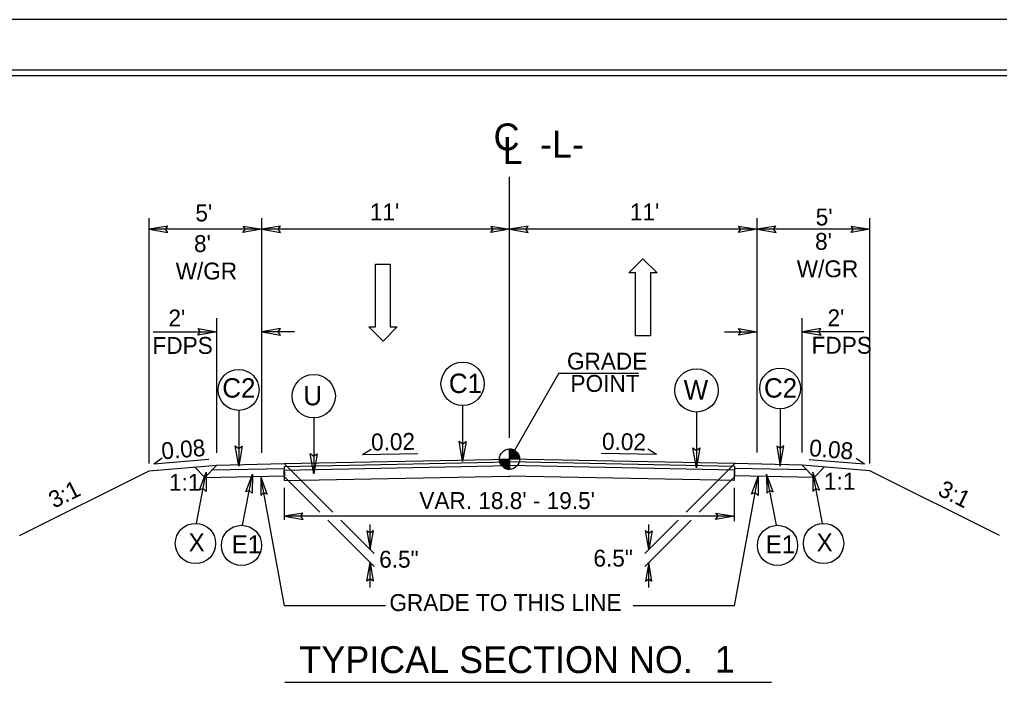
# Model space of a CAD drawing. Extents: x 60664 to 60833, y 51234 to 51344.
# Drawn here: x 60735.82 to 60779.32, y 51314.31 to 51344.41 of the extents above; entities that cross this region are included whole.
import ezdxf

# ---------------------------------------------------------------- set-up
doc = ezdxf.new("R2010")
doc.units = 0
for name, color, linetype in [('Exist XS Ground Line', 7, 'Continuous'), ('Prop Dimension', 7, 'Continuous'), ('Prop Dimension Text', 7, 'Continuous'), ('Prop Lane Arrow CELL', 7, 'Continuous'), ('Sheet Cutting Line CELL', 7, 'Continuous'), ('Sheet Plot Border Inside CELL', 7, 'Continuous'), ('Sheet Plot Border Outside CELL', 7, 'Continuous'), ('Sheet Typical CELL', 7, 'Continuous'), ('Typical Grade Point Symbol CELL', 7, 'Continuous'), ('Typical ID Circle CELL', 7, 'Continuous'), ('Typical Pavement Slope CELL', 7, 'Continuous'), ('Typical Pavement Slope Information CELL', 7, 'Continuous'), ('Typical Shoulder Slope CELL', 7, 'Continuous'), ('Typical Shoulder Slope Information CELL', 7, 'Continuous'), ('Typical Slope Point Local CELL', 7, 'Continuous'), ('Typical Terminator CELL', 7, 'Continuous'), ('Typical Text General CELL', 7, 'Continuous'), ('Typical Text Grade Point CELL', 7, 'Continuous'), ('Typical Text ID Circle CELL', 7, 'Continuous'), ('Typical Text Label CELL', 7, 'Continuous')]:
    doc.layers.add(name, color=color, linetype=linetype)

msp = doc.modelspace()

# ---------------------------------------------------------------- linework, layer by layer
at = {"layer": 'Exist XS Ground Line'}
for p, q in [((60747.573, 51324.403), (60757.576, 51324.603)), ((60747.577, 51323.941), (60747.573, 51324.403)), ((60767.567, 51324.403), (60757.568, 51324.603)), ((60767.557, 51323.941), (60767.567, 51324.403)), ((60747.575, 51323.941), (60757.585, 51324.141)), ((60767.557, 51323.941), (60757.559, 51324.141))]:
    msp.add_line(p, q, dxfattribs=at)
at = {"layer": 'Prop Dimension'}
for p, q in [((60757.572, 51325.837), (60757.572, 51337.419)), ((60746.572, 51325.17), (60746.572, 51335.597)), ((60768.572, 51325.189), (60768.572, 51335.597)), ((60746.572, 51335.097), (60741.572, 51335.097)), ((60757.572, 51335.097), (60746.572, 51335.097)), ((60768.572, 51335.097), (60757.572, 51335.097)), ((60773.572, 51335.097), (60768.572, 51335.097)), ((60744.572, 51325.17), (60744.572, 51331.152)), ((60770.572, 51325.189), (60770.572, 51331.152)), ((60741.755, 51330.542), (60744.572, 51330.542)), ((60748.03, 51330.542), (60746.572, 51330.542)), ((60767.114, 51330.542), (60768.572, 51330.542)), ((60773.298, 51330.542), (60770.572, 51330.542)), ((60747.572, 51324.689), (60749.729, 51322.533)), ((60767.571, 51324.689), (60765.414, 51322.533)), ((60747.575, 51318.373), (60746.528, 51324.126)), ((60747.575, 51324.106), (60749.148, 51322.532)), ((60767.559, 51324.106), (60765.986, 51322.533)), ((60767.566, 51318.373), (60768.613, 51324.126)), ((60747.575, 51322.194), (60747.575, 51323.616)), ((60767.557, 51322.132), (60767.557, 51323.617)), ((60767.557, 51322.351), (60747.575, 51322.351)), ((60749.502, 51322.179), (60751.556, 51320.125)), ((60750.082, 51322.179), (60751.556, 51320.705)), ((60765.632, 51322.179), (60763.578, 51320.125)), ((60765.061, 51322.179), (60763.587, 51320.705)), ((60751.379, 51320.882), (60751.379, 51321.992)), ((60763.764, 51320.882), (60763.764, 51321.992)), ((60751.379, 51319.192), (60751.379, 51320.302)), ((60763.755, 51319.192), (60763.755, 51320.302)), ((60752.068, 51318.373), (60747.575, 51318.373)), ((60767.566, 51318.373), (60763.068, 51318.373))]:
    msp.add_line(p, q, dxfattribs=at)
at = {"layer": 'Prop Dimension Text'}
for p, q in [((60741.572, 51324.689), (60741.572, 51335.597)), ((60773.572, 51324.689), (60773.572, 51335.597))]:
    msp.add_line(p, q, dxfattribs=at)
at = {"layer": 'Prop Lane Arrow CELL'}
for p, q in [((60751.621, 51330.763), (60751.621, 51333.555)), ((60751.621, 51333.555), (60752.28, 51333.555)), ((60752.28, 51333.555), (60752.28, 51330.763)), ((60762.872, 51333.157), (60763.49, 51333.785)), ((60763.49, 51333.785), (60764.128, 51333.157)), ((60763.171, 51333.157), (60762.872, 51333.157)), ((60763.171, 51330.365), (60763.171, 51333.157)), ((60764.128, 51333.157), (60763.829, 51333.157)), ((60763.829, 51333.157), (60763.829, 51330.365)), ((60751.96, 51330.135), (60751.322, 51330.763)), ((60751.322, 51330.763), (60751.621, 51330.763)), ((60752.579, 51330.763), (60751.96, 51330.135)), ((60752.28, 51330.763), (60752.579, 51330.763)), ((60763.829, 51330.365), (60763.171, 51330.365))]:
    msp.add_line(p, q, dxfattribs=at)
at = {"layer": 'Sheet Cutting Line CELL'}
msp.add_line((60832.821, 51344.408), (60664.421, 51344.408), dxfattribs=at)
at = {"layer": 'Sheet Plot Border Inside CELL'}
msp.add_lwpolyline([(60832.371, 51342.163), (60665.721, 51342.163), (60665.721, 51236.653), (60832.371, 51236.653)], close=True, dxfattribs=at)
at = {"layer": 'Sheet Plot Border Outside CELL'}
msp.add_lwpolyline([(60832.821, 51344.408), (60664.421, 51344.408), (60664.421, 51234.408), (60832.821, 51234.408)], close=True, dxfattribs=at)
at = {"layer": 'Sheet Typical CELL'}
msp.add_lwpolyline([(60831.121, 51341.908), (60681.121, 51341.908), (60681.121, 51236.908), (60831.121, 51236.908)], close=True, dxfattribs=at)
at = {"layer": 'Typical Grade Point Symbol CELL'}
for p, q in [((60757.572, 51324.889), (60757.572, 51325.337)), ((60757.124, 51324.889), (60757.572, 51324.889)), ((60757.571, 51324.442), (60757.572, 51324.889)), ((60757.572, 51324.889), (60757.571, 51324.442)), ((60758.02, 51324.889), (60757.572, 51324.889))]:
    msp.add_line(p, q, dxfattribs=at)
for points in [[(60757.576, 51325.337), (60757.576, 51325.337), (60757.576, 51324.889)], [(60757.585, 51325.337), (60757.585, 51324.889)], [(60757.594, 51325.336), (60757.594, 51324.889)], [(60757.603, 51325.336), (60757.603, 51324.889)], [(60757.612, 51325.335), (60757.612, 51324.889)], [(60757.621, 51325.334), (60757.621, 51324.889)], [(60757.63, 51325.333), (60757.63, 51324.889)], [(60757.639, 51325.332), (60757.639, 51324.889)], [(60757.648, 51325.331), (60757.648, 51324.889)], [(60757.657, 51325.329), (60757.657, 51324.889)], [(60757.666, 51325.327), (60757.666, 51324.889)], [(60757.675, 51325.325), (60757.675, 51324.889)], [(60757.683, 51325.323), (60757.683, 51324.889)], [(60757.692, 51325.32), (60757.692, 51324.889)], [(60757.701, 51325.318), (60757.701, 51324.889)], [(60757.71, 51325.315), (60757.71, 51324.889)], [(60757.719, 51325.312), (60757.719, 51324.889)], [(60757.728, 51325.309), (60757.728, 51324.889)], [(60757.737, 51325.305), (60757.737, 51324.889)], [(60757.746, 51325.301), (60757.746, 51324.889)], [(60757.755, 51325.297), (60757.755, 51324.889)], [(60757.764, 51325.293), (60757.764, 51324.889)], [(60757.773, 51325.289), (60757.773, 51324.889)], [(60757.782, 51325.284), (60757.782, 51324.889)], [(60757.791, 51325.279), (60757.791, 51324.889)], [(60757.8, 51325.274), (60757.8, 51324.889)], [(60757.809, 51325.269), (60757.809, 51324.889)], [(60757.818, 51325.263), (60757.818, 51324.889)], [(60757.827, 51325.257), (60757.827, 51324.889)], [(60757.836, 51325.25), (60757.836, 51324.889)], [(60757.845, 51325.244), (60757.845, 51324.889)], [(60757.854, 51325.237), (60757.854, 51324.889)], [(60757.863, 51325.23), (60757.863, 51324.889)], [(60757.871, 51325.222), (60757.871, 51324.889)], [(60757.88, 51325.214), (60757.88, 51324.889)], [(60757.889, 51325.205), (60757.889, 51324.889)], [(60757.898, 51325.196), (60757.898, 51324.889)], [(60757.907, 51325.186), (60757.907, 51324.889)], [(60757.916, 51325.175), (60757.916, 51324.889)], [(60757.925, 51325.164), (60757.925, 51324.889)], [(60757.934, 51325.152), (60757.934, 51324.889)], [(60757.126, 51324.889), (60757.126, 51324.841)], [(60757.135, 51324.889), (60757.135, 51324.788)], [(60757.144, 51324.889), (60757.144, 51324.756)], [(60757.153, 51324.889), (60757.153, 51324.729)], [(60757.162, 51324.889), (60757.162, 51324.708)], [(60757.171, 51324.889), (60757.171, 51324.689)], [(60757.18, 51324.889), (60757.18, 51324.673)], [(60757.189, 51324.889), (60757.189, 51324.657)], [(60757.198, 51324.889), (60757.198, 51324.643)], [(60757.207, 51324.889), (60757.207, 51324.63)], [(60757.216, 51324.889), (60757.216, 51324.618)], [(60757.225, 51324.889), (60757.225, 51324.607)], [(60757.234, 51324.889), (60757.234, 51324.596)], [(60757.243, 51324.889), (60757.243, 51324.586)], [(60757.252, 51324.889), (60757.252, 51324.576)], [(60757.261, 51324.889), (60757.261, 51324.567)], [(60757.27, 51324.889), (60757.27, 51324.559)], [(60757.279, 51324.889), (60757.279, 51324.551)], [(60757.288, 51324.889), (60757.288, 51324.543)], [(60757.297, 51324.889), (60757.297, 51324.536)], [(60757.306, 51324.889), (60757.306, 51324.529)], [(60757.314, 51324.889), (60757.314, 51324.523)], [(60757.323, 51324.889), (60757.323, 51324.517)], [(60757.332, 51324.889), (60757.332, 51324.511)], [(60757.341, 51324.889), (60757.341, 51324.505)], [(60757.35, 51324.889), (60757.35, 51324.5)], [(60757.359, 51324.889), (60757.359, 51324.496)], [(60757.368, 51324.889), (60757.368, 51324.491)], [(60757.377, 51324.889), (60757.377, 51324.487)], [(60757.386, 51324.889), (60757.386, 51324.483)], [(60757.395, 51324.889), (60757.395, 51324.479)], [(60757.404, 51324.889), (60757.404, 51324.475)], [(60757.413, 51324.889), (60757.413, 51324.471)], [(60757.422, 51324.889), (60757.422, 51324.468)], [(60757.431, 51324.889), (60757.431, 51324.465)], [(60757.44, 51324.889), (60757.44, 51324.462)], [(60757.449, 51324.889), (60757.449, 51324.46)], [(60757.458, 51324.889), (60757.458, 51324.457)], [(60757.467, 51324.889), (60757.467, 51324.455)], [(60757.476, 51324.889), (60757.476, 51324.453)], [(60757.485, 51324.889), (60757.485, 51324.451)], [(60757.493, 51324.889), (60757.493, 51324.449)], [(60757.502, 51324.889), (60757.502, 51324.448)], [(60757.511, 51324.889), (60757.511, 51324.446)], [(60757.52, 51324.889), (60757.52, 51324.445)], [(60757.529, 51324.889), (60757.529, 51324.444)], [(60757.538, 51324.889), (60757.538, 51324.443)], [(60757.547, 51324.889), (60757.547, 51324.443)], [(60757.556, 51324.889), (60757.556, 51324.442)], [(60757.565, 51324.889), (60757.565, 51324.442), (60757.565, 51324.442)], [(60757.943, 51325.139), (60757.943, 51324.889)], [(60757.952, 51325.125), (60757.952, 51324.889)], [(60757.961, 51325.11), (60757.961, 51324.889)], [(60757.97, 51325.094), (60757.97, 51324.889)], [(60757.979, 51325.075), (60757.979, 51324.889)], [(60757.988, 51325.054), (60757.988, 51324.889)], [(60757.997, 51325.03), (60757.997, 51324.889)], [(60758.006, 51324.999), (60758.006, 51324.889)], [(60758.015, 51324.953), (60758.015, 51324.889)]]:
    msp.add_lwpolyline(points, dxfattribs=at)
msp.add_circle((60757.572, 51324.889), 0.448, dxfattribs=at)
for start, end in [(359.9905, 89.9905), (179.9905, 269.9905)]:
    msp.add_arc((60757.572, 51324.889), 0.448, start, end, dxfattribs=at)
at = {"layer": 'Typical ID Circle CELL'}
for p, q in [((60745.556, 51327.056), (60745.556, 51324.581)), ((60755.492, 51327.271), (60755.492, 51324.786)), ((60765.872, 51326.983), (60765.872, 51324.497)), ((60769.588, 51327.121), (60769.588, 51324.581)), ((60748.878, 51326.725), (60748.878, 51324.239))]:
    msp.add_line(p, q, dxfattribs=at)
for centre, radius in [((60755.492, 51328.233), 0.962), ((60745.545, 51327.963), 0.907), ((60748.878, 51327.686), 0.962), ((60765.872, 51327.944), 0.962), ((60769.588, 51328.028), 0.907)]:
    msp.add_circle(centre, radius, dxfattribs=at)
at = {"layer": 'Typical Pavement Slope CELL'}
for p, q in [((60747.572, 51324.689), (60757.572, 51324.889)), ((60747.575, 51324.564), (60757.575, 51324.764)), ((60767.569, 51324.564), (60757.57, 51324.764)), ((60767.571, 51324.689), (60757.572, 51324.889)), ((60744.368, 51324.415), (60747.573, 51324.481)), ((60744.572, 51324.628), (60747.572, 51324.689)), ((60747.573, 51324.564), (60747.575, 51324.148)), ((60767.569, 51324.564), (60767.56, 51324.148)), ((60770.776, 51324.415), (60767.567, 51324.481)), ((60770.572, 51324.628), (60767.571, 51324.689)), ((60744.041, 51324.075), (60747.575, 51324.148)), ((60771.102, 51324.075), (60767.56, 51324.148))]:
    msp.add_line(p, q, dxfattribs=at)
at = {"layer": 'Typical Pavement Slope Information CELL'}
for p, q in [((60751.045, 51325.095), (60751.436, 51325.331)), ((60764.099, 51325.095), (60763.708, 51325.331)), ((60741.778, 51324.685), (60742.154, 51324.946)), ((60741.778, 51324.685), (60744.228, 51324.889)), ((60751.045, 51325.095), (60753.502, 51325.144)), ((60764.099, 51325.095), (60761.642, 51325.144)), ((60773.334, 51324.661), (60770.884, 51324.865)), ((60773.334, 51324.661), (60772.958, 51324.922))]:
    msp.add_line(p, q, dxfattribs=at)
at = {"layer": 'Typical Shoulder Slope CELL'}
for p, q in [((60741.572, 51324.378), (60744.572, 51324.628)), ((60744.042, 51324.076), (60743.591, 51324.546)), ((60744.042, 51324.076), (60744.572, 51324.628)), ((60770.572, 51324.628), (60771.102, 51324.076)), ((60773.572, 51324.378), (60770.572, 51324.628)), ((60771.553, 51324.546), (60771.102, 51324.076))]:
    msp.add_line(p, q, dxfattribs=at)
at = {"layer": 'Typical Slope Point Local CELL'}
for p, q in [((60735.821, 51321.502), (60741.572, 51324.378)), ((60779.323, 51321.502), (60773.572, 51324.378))]:
    msp.add_line(p, q, dxfattribs=at)
at = {"layer": 'Typical Terminator CELL'}
for points in [[(60742.4, 51335.24), (60741.572, 51335.097), (60742.405, 51334.95), (60742.299, 51335.097)], [(60745.744, 51335.24), (60746.572, 51335.097), (60745.739, 51334.95), (60745.845, 51335.097)], [(60747.4, 51335.24), (60746.572, 51335.097), (60747.405, 51334.95), (60747.299, 51335.097)], [(60756.744, 51335.24), (60757.572, 51335.097), (60756.739, 51334.95), (60756.845, 51335.097)], [(60758.4, 51335.24), (60757.572, 51335.097), (60758.405, 51334.95), (60758.299, 51335.097)], [(60767.744, 51335.24), (60768.572, 51335.097), (60767.739, 51334.95), (60767.845, 51335.097)], [(60769.4, 51335.24), (60768.572, 51335.097), (60769.405, 51334.95), (60769.299, 51335.097)], [(60772.744, 51335.24), (60773.572, 51335.097), (60772.739, 51334.95), (60772.845, 51335.097)], [(60743.744, 51330.685), (60744.572, 51330.542), (60743.739, 51330.395), (60743.845, 51330.542)], [(60747.4, 51330.685), (60746.572, 51330.542), (60747.405, 51330.395), (60747.299, 51330.542)], [(60767.744, 51330.685), (60768.572, 51330.542), (60767.739, 51330.395), (60767.845, 51330.542)], [(60771.4, 51330.685), (60770.572, 51330.542), (60771.405, 51330.395), (60771.299, 51330.542)], [(60755.646, 51325.676), (60755.492, 51324.786), (60755.334, 51325.681), (60755.492, 51325.568)], [(60745.71, 51325.472), (60745.556, 51324.581), (60745.398, 51325.476), (60745.556, 51325.363)], [(60766.026, 51325.388), (60765.872, 51324.497), (60765.714, 51325.393), (60765.872, 51325.279)], [(60769.434, 51325.472), (60769.588, 51324.581), (60769.746, 51325.476), (60769.588, 51325.363)], [(60749.031, 51325.13), (60748.878, 51324.239), (60748.72, 51325.135), (60748.878, 51325.021)], [(60746.817, 51323.337), (60746.528, 51324.126), (60746.533, 51323.281), (60746.659, 51323.411)], [(60768.324, 51323.337), (60768.613, 51324.126), (60768.608, 51323.281), (60768.483, 51323.411)], [(60748.403, 51322.493), (60747.575, 51322.351), (60748.408, 51322.204), (60748.302, 51322.351)], [(60766.729, 51322.493), (60767.557, 51322.351), (60766.725, 51322.204), (60766.831, 51322.351)], [(60751.237, 51321.71), (60751.379, 51320.882), (60751.527, 51321.715), (60751.379, 51321.609)], [(60763.907, 51321.71), (60763.764, 51320.882), (60763.617, 51321.715), (60763.764, 51321.609)], [(60751.236, 51319.474), (60751.379, 51320.302), (60751.526, 51319.469), (60751.379, 51319.575)], [(60763.898, 51319.474), (60763.755, 51320.302), (60763.608, 51319.469), (60763.755, 51319.575)]]:
    msp.add_lwpolyline(points, close=True, dxfattribs=at)
at = {"layer": 'Typical Text Grade Point CELL'}
for q in [(60757.572, 51324.889), (60763.297, 51328.71)]:
    msp.add_line((60759.759, 51328.71), q, dxfattribs=at)
at = {"layer": 'Typical Text ID Circle CELL'}
for p, q in [((60743.676, 51322.037), (60744.111, 51324.304)), ((60771.469, 51322.037), (60771.033, 51324.304)), ((60745.72, 51321.951), (60746.155, 51324.218)), ((60769.425, 51321.951), (60768.989, 51324.218))]:
    msp.add_line(p, q, dxfattribs=at)
for points in [[(60743.815, 51323.518), (60744.111, 51324.304), (60744.099, 51323.459), (60743.974, 51323.59)], [(60743.815, 51323.518), (60744.111, 51324.304), (60744.099, 51323.459), (60743.974, 51323.59)], [(60771.329, 51323.518), (60771.033, 51324.304), (60771.045, 51323.459), (60771.17, 51323.59)], [(60771.329, 51323.518), (60771.033, 51324.304), (60771.045, 51323.459), (60771.17, 51323.59)], [(60745.859, 51323.432), (60746.155, 51324.218), (60746.143, 51323.373), (60746.018, 51323.504)], [(60745.859, 51323.432), (60746.155, 51324.218), (60746.143, 51323.373), (60746.018, 51323.504)], [(60769.285, 51323.432), (60768.989, 51324.218), (60769.001, 51323.373), (60769.126, 51323.504)], [(60769.285, 51323.432), (60768.989, 51324.218), (60769.001, 51323.373), (60769.126, 51323.504)]]:
    msp.add_lwpolyline(points, close=True, dxfattribs=at)
for centre in [(60743.629, 51321.144), (60745.673, 51321.058), (60769.471, 51321.058), (60771.515, 51321.144)]:
    msp.add_circle(centre, 0.894, dxfattribs=at)
at = {"layer": 'Typical Text Label CELL'}
msp.add_line((60747.6, 51314.99), (60769.204, 51314.99), dxfattribs=at)

# ---------------------------------------------------------------- texts
at = {"layer": 'Prop Dimension Text'}
for s, height, p in [('C    ', 1.1936, (60756.864, 51338.602)), ('L', 1.194, (60757.264, 51338.001)), ('-L-', 1.1936, (60758.926, 51338.277)), ("5'", 0.75, (60743.626, 51335.449)), ("11'", 0.75, (60751.373, 51335.492)), ("11'", 0.75, (60762.918, 51335.492)), ("5'", 0.75, (60771.167, 51335.266)), ("8'", 0.75, (60743.564, 51334.087)), ("8'", 0.75, (60771.139, 51334.184)), ('W/GR', 0.75, (60742.75, 51332.868)), ('W/GR', 0.75, (60770.326, 51332.966)), ("2'", 0.75, (60742.428, 51330.782)), ("2'", 0.75, (60771.69, 51330.79)), ('FDPS', 0.75, (60741.723, 51329.564)), ('FDPS', 0.75, (60770.985, 51329.571)), ('1:1', 0.75, (60771.535, 51323.534)), ('1:1', 0.75, (60742.455, 51323.483)), ("VAR. 18.8' - 19.5'", 0.75, (60753.569, 51322.675)), ('6.5"', 0.75, (60751.787, 51320.071)), ('6.5"', 0.75, (60761.299, 51320.118))]:
    msp.add_text(s, height=height, dxfattribs=at).set_placement(p)
at = {"layer": 'Typical Pavement Slope Information CELL'}
for rotation, p in [(1.1457, (60751.433, 51325.268)), (358.8543, (60761.673, 51325.309))]:
    msp.add_text('0.02', height=0.75, rotation=rotation, dxfattribs=at).set_placement(p)
at = {"layer": 'Typical Shoulder Slope Information CELL'}
for rotation, p in [(4.7615, (60742.146, 51324.875)), (355.2385, (60770.854, 51325.027))]:
    msp.add_text('0.08', height=0.75, rotation=rotation, dxfattribs=at).set_placement(p)
at = {"layer": 'Typical Slope Point Local CELL'}
for rotation, p in [(26.5651, (60737.101, 51322.561)), (333.4349, (60776.288, 51323.439))]:
    msp.add_text(' 3:1 ', height=0.75, rotation=rotation, dxfattribs=at).set_placement(p)
at = {"layer": 'Typical Text General CELL'}
msp.add_text('GRADE TO THIS LINE', height=0.75, dxfattribs=at).set_placement((60752.239, 51318.146))
at = {"layer": 'Typical Text Grade Point CELL'}
for s, p in [('GRADE', (60760.123, 51328.866)), ('POINT', (60760.28, 51327.878))]:
    msp.add_text(s, height=0.75, dxfattribs=at).set_placement(p)
at = {"layer": 'Typical Text ID Circle CELL'}
for s, height, p in [('C1', 0.8608, (60754.88, 51327.826)), ('C2', 0.8608, (60744.821, 51327.622)), ('W', 0.861, (60765.306, 51327.538)), ('C2', 0.8608, (60768.871, 51327.622)), ('U', 0.861, (60748.42, 51327.28)), ('X', 0.8, (60743.327, 51320.79)), ('E1', 0.8004, (60745.235, 51320.704)), ('E1', 0.8004, (60768.948, 51320.704)), ('X', 0.8, (60771.208, 51320.79))]:
    msp.add_text(s, height=height, dxfattribs=at).set_placement(p)
at = {"layer": 'Typical Text Label CELL'}
for s, height, p in [('TYPICAL SECTION NO.  ', 1.19356, (60748.24, 51315.39)), ('1', 1.194, (60766.692, 51315.405))]:
    msp.add_text(s, height=height, dxfattribs=at).set_placement(p)

doc.saveas('drawing.dxf')
